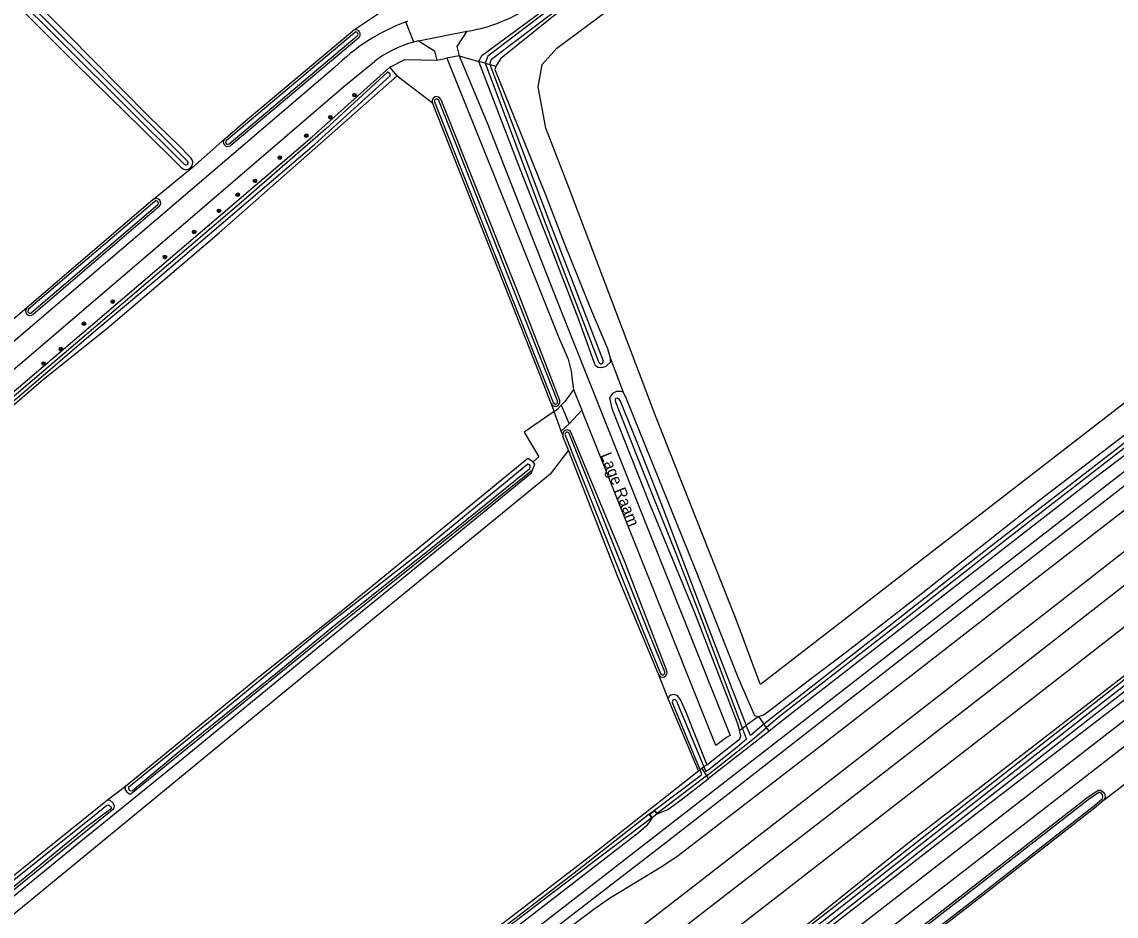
# Model space of a CAD drawing. Extents: x 141000 to 143000, y 400580 to 403500.
# Drawn here: x 142605.5 to 142848.1, y 403009.7 to 403208 of the extents above; entities that cross this region are included whole.
import ezdxf

# ---------------------------------------------------------------- set-up
doc = ezdxf.new("R2010")
doc.units = 0
for name, color, linetype in [('gg-afsc-muur', 7, 'Continuous'), ('gg-anno-openbare ruimte label', 7, 'Continuous'), ('gg-knt-bronhoudergrens', 7, 'Continuous'), ('gg-knt-onverhard', 7, 'Continuous'), ('gg-knt-verharding', 7, 'Continuous'), ('gg-kntw-bovenkant insteek waterloop', 7, 'Continuous'), ('gg-kntw-waterlijn', 7, 'Continuous'), ('gt-grn-vlakafsluiter', 7, 'Continuous'), ('gt-symb-boom', 7, 'Continuous'), ('gx-grn-maaiveld', 7, 'Continuous')]:
    doc.layers.add(name, color=color, linetype=linetype)

# ---------------------------------------------------------------- blocks, each defined once
blk = doc.blocks.new('gt0-BOOM')
at = {"layer": 'gt-symb-boom'}
for radius in [0.4, 0.2]:
    blk.add_circle((0, 0), radius, dxfattribs=at)

msp = doc.modelspace()

# ---------------------------------------------------------------- linework, layer by layer
at = {"layer": 'gg-afsc-muur'}
for p, q in [((142744.57, 403032.33), (142745.75, 403033.23)), ((142745.17, 403031.55), (142745.24, 403031.61)), ((142746.35, 403032.48), (142746.28, 403032.41))]:
    msp.add_line(p, q, dxfattribs=at)
for points in [[(142745.17, 403031.55), (142744.83, 403031.99), (142744.57, 403032.33)], [(142745.24, 403031.61), (142744.71, 403032.31), (142745.74, 403033.09), (142746.28, 403032.41)], [(142746.35, 403032.48), (142746.01, 403032.9), (142745.75, 403033.23)]]:
    msp.add_lwpolyline(points, dxfattribs=at)
at = {"layer": 'gg-knt-bronhoudergrens'}
for p, q in [((142687.67, 403211.8), (142679.2, 403206.19)), ((142650.46, 403182.09), (142643.28, 403175.7)), ((142643.28, 403175.7), (142634.66, 403168.61)), ((142606.6, 403144.58), (142599.46, 403138.52)), ((142624.49, 403035.49), (142628.48, 403038.54))]:
    msp.add_line(p, q, dxfattribs=at)
for points in [[(142860.35, 403218.34), (142869.79, 403206.95), (142881.11, 403192.84), (142892.74, 403178.21), (142896.1, 403173.53), (142898.31, 403170.27), (142899.78, 403165.17), (142896.95, 403159.78), (142769.2, 403061.07), (142769.07, 403061.42)], [(142769.07, 403061.42), (142763.86, 403075.51), (142746.12, 403120.26), (142725.92, 403173.39), (142721.65, 403184.43), (142719.96, 403193.57), (142720.81, 403198.52), (142724.1, 403202.14), (142744.38, 403217.33)], [(142723.48, 403121.63), (142716.84, 403117.01), (142720.13, 403111.55), (142718.78, 403110.37)], [(142726.66, 403113.04), (142722.58, 403107.7), (142684.85, 403076.84), (142643.77, 403043.04), (142579.48, 402990.32), (142536.68, 402955.33), (142533.64, 402956.99)], [(142540.27, 402963.78), (142540.9, 402963.31), (142542.17, 402964.39), (142542.45, 402964.07), (142590.47, 403003.44), (142618.53, 403026.38), (142641.27, 403044.79), (142676.95, 403074.08), (142690.52, 403085.2), (142718.54, 403108.09), (142718.69, 403108.67)]]:
    msp.add_lwpolyline(points, dxfattribs=at)
at = {"layer": 'gg-knt-onverhard'}
for p, q in [((142688.71, 403196.01), (142696.52, 403190.05)), ((142643.28, 403175.7), (142643.12, 403175.9)), ((142845.46, 403035.54), (142852.49, 403040.97))]:
    msp.add_line(p, q, dxfattribs=at)
at = {"layer": 'gg-knt-verharding'}
for p, q in [((142693.41, 403203.77), (142704.15, 403205.91)), ((142697.5, 403199.52), (142699.63, 403199.93)), ((142702.42, 403200.46), (142699.71, 403199.94)), ((142727.79, 403126.51), (142729.62, 403121.94)), ((142725.06, 403117.25), (142723.48, 403121.63)), ((142725.06, 403123.03), (142726.81, 403118.88)), ((142729.62, 403121.94), (142726.81, 403118.88)), ((142725.06, 403117.25), (142726.81, 403118.88))]:
    msp.add_line(p, q, dxfattribs=at)
for points in [[(142714.11, 402999.75), (142748.22, 403026.06), (142789.16, 403058), (142819.88, 403081.86), (142852.85, 403107.41), (142889.13, 403135.74), (142931.28, 403168.26), (142964.03, 403193.78), (142991.64, 403215.21), (143000, 403221.81)], [(142988.29, 403215.69), (142947.1, 403183.7), (142909.91, 403154.91), (142862.79, 403118.26), (142815.53, 403081.55), (142779.77, 403053.8), (142745.55, 403027.19), (142712.4, 403001.45)], [(142715.38, 402998.49), (142722.74, 403004.11), (142732.3, 403011.32), (142735.78, 403013.7), (142742.31, 403017.73), (142747.6, 403020.92), (142750.95, 403023.21), (142782.44, 403047.4), (142805.27, 403065.14), (142827.57, 403082.45), (142854.05, 403103.02), (142878.14, 403121.71), (142900.99, 403139.43), (142930.07, 403161.98), (142953.7, 403180.33), (142977.49, 403198.76), (142999.29, 403215.74), (143000, 403216.3)], [(142704.15, 403205.91), (142701.92, 403202.55), (142702.42, 403200.46)], [(142722.31, 402991.56), (142728.58, 402996.43), (142755.34, 403017.16), (142787.6, 403042.21), (142809.55, 403059.24), (142832.4, 403077), (142858.36, 403097.22), (142882.05, 403115.58), (142905.3, 403133.57), (142934.37, 403156.14), (142957.84, 403174.43), (142981.63, 403192.83), (143000, 403207.14)], [(142693.41, 403203.77), (142696.99, 403201.54), (142697.5, 403199.52)], [(142479.87, 403025.12), (142638.66, 403160.83), (142676.84, 403193.65), (142683.65, 403199.18)], [(142699.71, 403199.94), (142710.41, 403173.33), (142724.48, 403138.15), (142726.57, 403133.18), (142727.24, 403130.56), (142727.52, 403128.6), (142727.79, 403126.51)], [(142702.42, 403200.46), (142708.64, 403185.59), (142724.16, 403146.1), (142762.49, 403049.8), (142761.73, 403049.35), (142759.37, 403047.59), (142729.62, 403121.94)], [(142726.55, 402987.33), (142759.79, 403013.15), (142794.3, 403039.83), (142824.94, 403063.63), (142855.79, 403087.68), (142879.04, 403105.82), (142904.88, 403125.97), (142938.26, 403151.99), (142964.63, 403172.56), (142986.31, 403189.4), (143000, 403200.06)], [(142674.81, 403197.87), (142603.73, 403137.12), (142467.85, 403021.07), (142458.4, 403012.83)], [(142731.73, 402982.16), (142765.05, 403007.95), (142798.49, 403033.99), (142828.71, 403057.43), (142858.79, 403080.8), (142882.19, 403099.08), (142907.55, 403118.92), (142942.28, 403146.03), (142968.81, 403166.64), (142983.33, 403177.84), (142986.06, 403179.91), (142989.29, 403182.19), (142990.88, 403183.32), (142993.31, 403184.82), (143000, 403188.82)], [(142727.79, 403126.51), (142726.75, 403125.02), (142725.75, 403123.77), (142725.06, 403123.03)], [(142723.48, 403121.63), (142724.37, 403122.3), (142725.06, 403123.03)]]:
    msp.add_lwpolyline(points, dxfattribs=at)
msp.add_arc((142698.62, 403240.77), 35.3, 279.016, 308.6824, dxfattribs=at)
at = {"layer": 'gg-kntw-bovenkant insteek waterloop'}
for p, q in [((142680.17, 403204.48), (142651.78, 403180.6)), ((142688.71, 403196.01), (142687.06, 403197.98)), ((142717.26, 403137.51), (142696.52, 403190.05)), ((142634.63, 403168.58), (142606.6, 403144.58)), ((142635.93, 403167.06), (142607.97, 403143.12)), ((142721.12, 403127.74), (142717.26, 403137.51)), ((142722.83, 403123.41), (142721.12, 403127.74)), ((142726.66, 403113.04), (142725.44, 403116.16)), ((142755.5, 403041.93), (142748.8, 403057.91))]:
    msp.add_line(p, q, dxfattribs=at)
for points in [[(142547.36, 403273.24), (142563.78, 403256.69), (142581.71, 403239.05), (142615.56, 403205.33), (142633.58, 403187.1), (142640.07, 403180.8), (142642.94, 403177.82)], [(142640.83, 403175.69), (142632.08, 403184.36), (142617.37, 403198.78), (142602.25, 403214), (142584.13, 403231.28), (142569.16, 403246.61), (142552.14, 403263.78), (142545.24, 403271.12)], [(142706.76, 403199.23), (142707.49, 403200.53), (142728.18, 403215.79)], [(142982.91, 403216.29), (142982.9, 403215.84), (142982.62, 403215.24), (142982.07, 403214.43), (142952.64, 403191.36), (142921.77, 403167.73), (142894.62, 403146.27), (142866.83, 403124.65), (142842.93, 403106.54), (142816.01, 403085.59), (142775.72, 403054.36), (142771.15, 403050.77)], [(142729.39, 403214.2), (142711.65, 403199.89), (142710.56, 403198.2)], [(142650.46, 403182.09), (142655.54, 403186.38), (142678.88, 403206.01)], [(142735.94, 403133.54), (142735.91, 403132.47), (142735.26, 403131.88), (142734.95, 403131.62), (142734.29, 403131.34), (142733.83, 403131.28), (142733.28, 403131.35), (142732.68, 403131.77), (142732.05, 403133.3), (142730.74, 403137.09), (142728.87, 403142.14), (142722.84, 403157.9), (142715.89, 403175.54), (142706.76, 403199.23)], [(142481.78, 403021.02), (142481.71, 403021.74), (142482.3, 403022.59), (142554.77, 403084.41), (142620.69, 403140.5), (142669.87, 403182.48), (142687.06, 403197.98)], [(142483.71, 403020.26), (142525.74, 403056.39), (142561.18, 403086.54), (142610.32, 403128.81), (142624.25, 403139.94), (142649.26, 403161.21), (142688.71, 403196.01)], [(142710.56, 403198.2), (142710.37, 403197.39), (142715.9, 403183.78), (142721.53, 403169.88), (142725.7, 403158.94), (142731.75, 403143.92), (142735.29, 403135.56), (142735.94, 403133.54)], [(142698.38, 403190.77), (142715.23, 403148.61), (142724.7, 403124.12)], [(142768.77, 403054.01), (142769.93, 403054.36), (142770.84, 403055), (142780.23, 403062.31), (142787.69, 403067.9), (142804.84, 403081.19), (142831.15, 403102.02), (142888.02, 403145.61), (142913.07, 403164.76)], [(142936.5, 403128.66), (142931.38, 403123.84), (142917.07, 403111.21), (142866.41, 403070.34), (142814.08, 403030.15), (142765, 402992.1), (142702.74, 402944.32), (142636.14, 402892.61), (142573.7, 402843.97), (142551.1, 402826.68), (142505.39, 402791.3), (142496.71, 402784.39)], [(142738.76, 403125.88), (142738.24, 403126.06), (142737.3, 403126.03), (142736.46, 403125.57), (142735.78, 403124.67), (142736.3, 403122.29), (142744.73, 403100.99), (142754.57, 403077.06), (142763.98, 403052.85), (142764.58, 403050.95)], [(142738.76, 403125.88), (142739.42, 403124.47), (142754.74, 403086.69), (142764.19, 403062.69), (142767.9, 403054.25), (142768.77, 403054.01)], [(142748.46, 403064.11), (142739.14, 403088.25), (142727.3, 403116.9)], [(142628.48, 403038.54), (142658.35, 403063.02), (142678.12, 403078.83), (142717.67, 403111.29), (142718.45, 403110.76), (142718.78, 403110.37)], [(142746.61, 403063.35), (142737.64, 403084.97), (142726.66, 403113.04)], [(142628.48, 403038.54), (142628.3, 403037.86), (142628.71, 403037.4), (142629.25, 403036.87), (142629.62, 403036.88), (142675.84, 403074.35), (142718.69, 403108.67)], [(142718.78, 403110.37), (142719.14, 403109.95), (142718.69, 403108.67)], [(142748.8, 403057.91), (142749.03, 403058.56), (142749.37, 403058.8), (142750.08, 403058.95), (142750.76, 403058.67), (142751.57, 403057.44), (142752.61, 403055.18), (142757.32, 403043.31)], [(142757.32, 403043.31), (142764.62, 403049.08), (142764.91, 403049.71), (142764.69, 403050.59), (142764.58, 403050.95)], [(142771.15, 403050.77), (142771.05, 403050.7), (142757.65, 403040.19)], [(142428.79, 402814.76), (142429.16, 402814.41), (142430.72, 402813.07), (142433.76, 402810.99), (142437.8, 402809.46), (142440.98, 402808.87), (142443.89, 402808.8), (142446.09, 402808.89), (142448.61, 402809.52), (142451.95, 402811.01), (142454.52, 402812.19), (142459.9, 402815.61), (142491.15, 402839.34), (142515.23, 402857.34), (142521.13, 402860.91), (142544.53, 402878.21), (142590.32, 402913.85), (142635.9, 402949.08), (142683.62, 402986.21), (142733.22, 403024.46), (142755.5, 403041.93)], [(142746.35, 403032.48), (142746.55, 403032.48), (142748.7, 403033.4), (142751.38, 403035.28), (142757.65, 403040.19)], [(142785.7, 402992.08), (142786.52, 402993.26), (142793.36, 402998.39), (142841.6, 403035.94), (142844.11, 403037.67), (142844.69, 403037.67), (142845.16, 403037.32), (142845.57, 403036.81), (142845.68, 403036.04), (142845.46, 403035.54)], [(142538.19, 402964.21), (142537.69, 402965.1), (142569.58, 402990.98), (142597.09, 403013.47), (142624.49, 403035.49)], [(142624.49, 403035.49), (142624.99, 403035.43), (142625.64, 403034.86), (142625.93, 403034.22), (142625.87, 403033.78), (142625.64, 403033.36), (142625.12, 403032.95), (142562.37, 402982.09), (142540.27, 402963.78)], [(142845.46, 403035.54), (142843.64, 403033.98), (142817.19, 403013.27), (142788.78, 402991.34), (142787.23, 402989.66), (142786.84, 402987.94), (142802.59, 402918.5), (142810.84, 402870.89)], [(142745.17, 403031.55), (142745.12, 403031.38), (142745.05, 403031.28), (142744.8, 403030.87), (142743.96, 403029.76), (142742.22, 403028.2), (142710.29, 403003.56)]]:
    msp.add_lwpolyline(points, dxfattribs=at)
for centre, radius, start, end in [((142679.52, 403205.25), 0.996, 108.572, 130.0763), ((142679.52, 403205.24), 1, 310.1058, 108.7113), ((142697.45, 403190.41), 1, 21.1423, 201.1095), ((142651.14, 403181.36), 1, 133.2326, 310.1154), ((142641.89, 403176.75), 1.5, 325.197, 45.1649), ((142641.89, 403176.75), 1.5, 225.1872, 325.1926), ((142635.28, 403167.82), 1, 310.5759, 128.3456), ((142607.32, 403143.88), 1, 136.3313, 310.5856), ((142723.76, 403123.76), 1, 201.0807, 21.1384), ((142726.37, 403116.53), 1, 21.8385, 189.3794), ((142726.39, 403116.53), 1.02, 189.4338, 201.5861), ((142747.54, 403063.73), 1, 202.7985, 22.3046)]:
    msp.add_arc(centre, radius, start, end, dxfattribs=at)
at = {"layer": 'gg-kntw-waterlijn'}
for p, q in [((142650.82, 403181.74), (142679.2, 403205.63)), ((142651.46, 403180.98), (142679.85, 403204.86)), ((142696.98, 403190.23), (142723.3, 403123.59)), ((142724.23, 403123.95), (142697.92, 403190.59)), ((142634.95, 403168.2), (142606.99, 403144.26)), ((142635.6, 403167.44), (142607.65, 403143.51)), ((142755.83, 403042.18), (142749.71, 403057.05)), ((142750.63, 403057.43), (142756.68, 403042.82)), ((142757.24, 403040.83), (142746.35, 403032.48))]:
    msp.add_line(p, q, dxfattribs=at)
for points in [[(142641.53, 403176.4), (142589.01, 403228.64), (142545.95, 403271.82)], [(142642.24, 403177.11), (142589.72, 403229.35), (142546.65, 403272.53)], [(142728.48, 403215.39), (142708.78, 403200.36), (142708.23, 403198.83)], [(142709.2, 403198.57), (142709.62, 403199.74), (142729.09, 403214.6)], [(142769.98, 403052.32), (142770.01, 403052.35), (142777.08, 403057.95), (142797.39, 403073.82), (142819.79, 403091.42), (142848.12, 403113.27), (142871.51, 403131.66), (142892.65, 403147.36), (142912.34, 403162.35), (142932.84, 403178.62), (142961.7, 403201.08), (142978.65, 403213.76)], [(142973.71, 403209.13), (142961.64, 403199.83), (142945.01, 403186.74), (142926.48, 403172.51), (142907.13, 403157.34), (142882.92, 403138.81), (142866.43, 403126.61), (142850.45, 403113.9), (142823.81, 403093.28), (142800.12, 403074.67), (142777.43, 403057.11), (142773.43, 403053.99), (142770.56, 403051.53)], [(142708.23, 403198.83), (142721.48, 403163.46), (142733.43, 403132.5)], [(142709.2, 403198.57), (142722.42, 403163.81), (142734.37, 403132.86)], [(142539.75, 403069.03), (142571.55, 403096.47), (142590.52, 403112.78), (142621.9, 403139.63), (142635.03, 403150.68), (142670.33, 403180.77), (142687.14, 403196.02), (142687.17, 403196.46), (142686.58, 403196.81), (142672.82, 403184.17), (142653.56, 403167.53), (142576.08, 403101.46), (142534.01, 403065.68), (142512.19, 403047.04), (142485.11, 403024.16), (142482.37, 403021.67), (142482.62, 403021.36), (142482.89, 403021.25), (142483.2, 403021.26), (142486.53, 403023.79), (142515.15, 403048.22), (142539.75, 403069.03)], [(142935.44, 403129.72), (142928.34, 403122.78), (142918.97, 403114.88), (142907.54, 403105.66), (142898.61, 403098.66), (142841.86, 403054.57), (142811.13, 403030.58), (142777.76, 403004.42), (142763.39, 402993.26), (142702.88, 402946.48), (142640.13, 402897.73), (142594.02, 402862.01), (142506.27, 402793.88), (142495.78, 402785.57)], [(142496.4, 402784.78), (142506.88, 402793.09), (142594.63, 402861.22), (142640.74, 402896.94), (142703.49, 402945.69), (142764, 402992.47), (142778.37, 403003.63), (142811.75, 403029.79), (142842.48, 403053.78), (142899.22, 403097.87), (142908.16, 403104.88), (142919.61, 403114.11), (142929.02, 403122.04), (142936.15, 403129.01)], [(142765.23, 403051.4), (142756.32, 403075.3), (142750.58, 403089.88), (142741.5, 403112.61), (142737.16, 403123.7), (142737.07, 403124.31), (142737.19, 403124.55), (142737.45, 403124.65), (142737.72, 403124.47), (142738.18, 403123.72), (142741.73, 403115.03), (142747.12, 403101.39), (142752.71, 403086.82), (142758.46, 403071.69), (142766.07, 403052.03)], [(142725.9, 403116.34), (142743.24, 403072.9), (142747.07, 403063.54)], [(142748, 403063.92), (142744.16, 403073.28), (142726.83, 403116.72)], [(142631.98, 403040.62), (142629.15, 403038.25), (142629.13, 403037.95), (142629.29, 403037.64), (142629.65, 403037.51), (142629.98, 403037.56), (142640.83, 403046.58), (142662.55, 403064.15), (142674.99, 403074.4), (142699.11, 403093.62), (142718.12, 403108.98), (142718.2, 403109.32), (142718.14, 403109.61), (142717.84, 403109.88), (142717.67, 403109.94), (142692.81, 403089.56), (142672.74, 403073.84), (142651.18, 403056.13), (142631.98, 403040.62)], [(142756.68, 403042.82), (142757.12, 403041.77), (142757.82, 403042.3), (142764.03, 403047.28), (142766.12, 403049.05), (142765.23, 403051.4)], [(142757.24, 403040.83), (142758.59, 403041.86), (142767.83, 403049.18), (142770.56, 403051.53)], [(142769.98, 403052.32), (142767.02, 403049.81), (142766.07, 403052.03)], [(142745.75, 403033.23), (142756.26, 403041.12), (142755.83, 403042.18)], [(142810.3, 402871.05), (142802.1, 402918.4), (142786.33, 402987.94), (142786.77, 402989.91), (142788.44, 402991.71), (142816.89, 403013.66), (142843.32, 403034.37), (142845.05, 403035.84), (142845.16, 403036.11), (142845.09, 403036.61), (142844.81, 403036.96), (142844.52, 403037.17), (142844.27, 403037.17), (142841.89, 403035.54), (142793.67, 402998), (142786.89, 402992.91), (142786.11, 402991.8), (142785.55, 402991), (142785.14, 402988.76), (142785.31, 402988.19), (142802.64, 402905.51), (142809.16, 402870.81)], [(142625.28, 403033.65), (142625.05, 403033.36), (142619.89, 403029.51), (142597.43, 403011.15), (142568.69, 402987.89), (142544.72, 402968.43), (142540.05, 402964.49), (142539.65, 402964.74), (142539.45, 402965.5), (142549.26, 402973.28), (142601.88, 403016.34), (142622.36, 403032.73), (142624.33, 403034.34), (142624.73, 403034.38), (142625.08, 403034.13), (142625.31, 403033.87), (142625.28, 403033.65)], [(142744.57, 403032.33), (142728.63, 403019.78), (142695.22, 402994.06), (142654.3, 402962.08), (142624.33, 402938.82), (142599.21, 402919.43), (142575.39, 402900.86), (142546.06, 402877.97)], [(142745.17, 403031.55), (142723.57, 403015.23), (142709.45, 403004.42)]]:
    msp.add_lwpolyline(points, dxfattribs=at)
for centre, start, end in [((142679.52, 403205.24), 310.1951, 130.0759), ((142697.45, 403190.41), 21.1526, 201.1526), ((142651.14, 403181.36), 130.0847, 310.0987), ((142641.89, 403176.75), 225.0806, 45.0815), ((142635.28, 403167.82), 310.6375, 130.5278), ((142607.32, 403143.88), 130.6199, 310.6199), ((142733.9, 403132.68), 201.0905, 21.1079), ((142723.76, 403123.76), 201.0905, 21.1079), ((142726.37, 403116.53), 21.8748, 201.7706), ((142747.54, 403063.73), 202.2368, 22.3239), ((142750.17, 403057.24), 22.3454, 202.3214)]:
    msp.add_arc(centre, 0.5, start, end, dxfattribs=at)
at = {"layer": 'gt-grn-vlakafsluiter'}
for p, q in [((142702.42, 403200.46), (142706.76, 403199.23)), ((142708.23, 403198.83), (142706.76, 403199.23)), ((142708.23, 403198.83), (142709.2, 403198.57)), ((142709.2, 403198.57), (142710.56, 403198.2)), ((142735.94, 403133.54), (142738.76, 403125.88)), ((142725.38, 403116.37), (142725.06, 403117.25)), ((142748.8, 403057.91), (142746.61, 403063.35)), ((142768.77, 403054.01), (142766.07, 403052.03)), ((142768.77, 403054.01), (142769.98, 403052.32)), ((142764.58, 403050.95), (142765.23, 403051.4)), ((142765.23, 403051.4), (142766.07, 403052.03)), ((142770.56, 403051.53), (142769.98, 403052.32)), ((142771.15, 403050.77), (142770.56, 403051.53)), ((142757.32, 403043.31), (142756.68, 403042.82)), ((142755.5, 403041.93), (142755.83, 403042.18)), ((142756.21, 403042.47), (142755.83, 403042.18)), ((142756.68, 403042.82), (142756.21, 403042.47)), ((142756.21, 403042.47), (142757.24, 403040.83)), ((142757.24, 403040.83), (142757.65, 403040.19))]:
    msp.add_line(p, q, dxfattribs=at)
for points in [[(142687.06, 403197.98), (142690.39, 403199.68), (142697.5, 403199.52)], [(142723.48, 403121.63), (142723.31, 403122.08), (142722.83, 403123.41)]]:
    msp.add_lwpolyline(points, dxfattribs=at)
at = {"layer": 'gx-grn-maaiveld'}
for p, q in [((142692.36, 403203.52), (142690.6, 403207.98)), ((142699.71, 403199.94), (142699.63, 403199.93)), ((142634.66, 403168.61), (142634.63, 403168.58)), ((142784.18, 403002.2), (142917.58, 403105.74)), ((142745.24, 403031.61), (142746.28, 403032.41))]:
    msp.add_line(p, q, dxfattribs=at)
for points in [[(142936.85, 403119.07), (142933.75, 403115.88), (142926.24, 403108.06), (142924.55, 403106.44), (142922.46, 403104.54), (142905.26, 403090.28), (142786.61, 402998.22)], [(142896.85, 403098.91), (142888.36, 403092.83), (142844.4, 403058.72), (142801.85, 403025.78), (142769.46, 402999.66), (142738.31, 402975.59)], [(142896.85, 403098.91), (142898.73, 403099.75), (142871.22, 403078.82), (142832.44, 403048.43), (142794.52, 403018.78), (142752.9, 402986.33), (142738.83, 402975.07)]]:
    msp.add_lwpolyline(points, dxfattribs=at)
for centre, radius, start, end in [((142698.12, 403188.2), 21.17, 109.6443, 110.8185), ((142706.15, 403166.35), 44.44, 110.4829, 134.8355), ((142698.35, 403180.59), 23.7, 104.647, 128.3409), ((142698.68, 403179.19), 25.14, 102.0841, 104.5486)]:
    msp.add_arc(centre, radius, start, end, dxfattribs=at)

# ---------------------------------------------------------------- block references
at = {"layer": 'gt-symb-boom'}
for p in [(142679.23, 403191.74), (142673.88, 403186.85), (142668.57, 403182.75), (142662.68, 403177.9), (142657.18, 403172.75), (142653.36, 403169.67), (142649.18, 403166.1), (142643.71, 403161.42), (142637.19, 403155.88), (142625.63, 403145.98), (142619.25, 403141.07), (142614.15, 403135.45), (142610.32, 403132.24)]:
    msp.add_blockref('gt0-BOOM', p, dxfattribs=at)

# ---------------------------------------------------------------- texts
at = {"layer": 'gg-anno-openbare ruimte label'}
msp.add_text('Lage Raam', height=2.5, rotation=291.8, dxfattribs=at).set_placement((142733.74, 403111.94))

doc.saveas('drawing.dxf')
